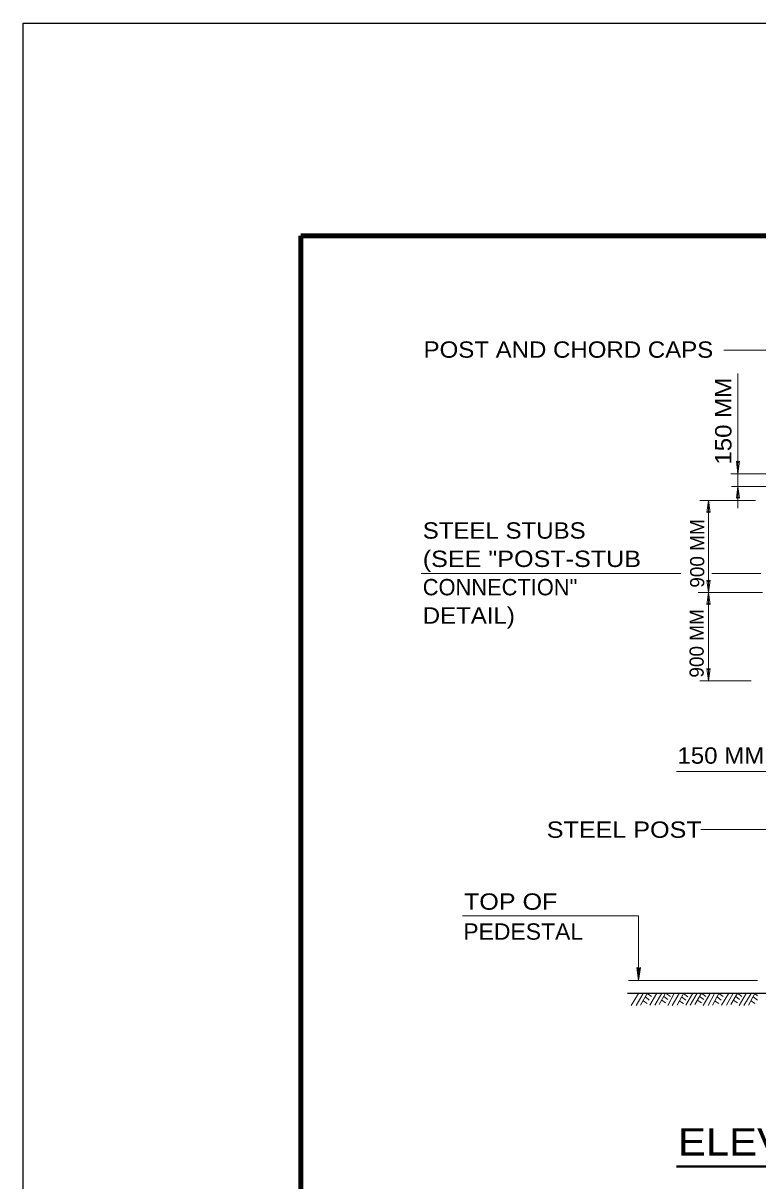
# Model space of a CAD drawing. Extents: x 312601.858 to 312602.699, y 144420.109 to 144420.704.
# Drawn here: x 312601.8578 to 312601.9927, y 144420.4911 to 144420.7035 of the extents above; entities that cross this region are included whole.
import ezdxf
from ezdxf.enums import TextEntityAlignment as Align

# ---------------------------------------------------------------- set-up
doc = ezdxf.new("R2010")
doc.units = 0
doc.header["$LTSCALE"] = 0.0012
for name, color, linetype, lineweight in [('1', 7, 'Continuous', 13), ('2', 7, 'Continuous', 25), ('39', 7, 'Continuous', 13)]:
    doc.layers.add(name, color=color, linetype=linetype, lineweight=lineweight)

msp = doc.modelspace()

# ---------------------------------------------------------------- hatches: boundary and pattern name
at = {"layer": '39'}
msp.add_hatch(color=256, dxfattribs=at).paths.add_polyline_path([(312601.9708, 144420.53), (312601.9712, 144420.5302), (312601.9708, 144420.5278), (312601.9705, 144420.5302)])

# ---------------------------------------------------------------- linework, layer by layer
at = {"layer": '1'}
for p, q in [((312601.9865, 144420.6435), (312601.9982, 144420.6435)), ((312601.9878, 144420.6208), (312601.9952, 144420.6208)), ((312601.9879, 144420.6185), (312601.9952, 144420.6185)), ((312601.9821, 144420.6159), (312601.9923, 144420.6159)), ((312601.9309, 144420.6025), (312601.9786, 144420.6025)), ((312601.9843, 144420.6025), (312601.9933, 144420.6025)), ((312601.9818, 144420.599), (312601.9936, 144420.599)), ((312601.9821, 144420.5828), (312601.9915, 144420.5828)), ((312601.9823, 144420.5555), (312601.9994, 144420.5555)), ((312601.969, 144420.5278), (312601.9927, 144420.5278)), ((312601.9695, 144420.5232), (312601.9708, 144420.5254)), ((312601.9704, 144420.5232), (312601.9717, 144420.5254)), ((312601.9712, 144420.5233), (312601.9724, 144420.5254)), ((312601.9724, 144420.5254), (312601.9732, 144420.5249)), ((312601.9729, 144420.5233), (312601.9742, 144420.5255)), ((312601.9738, 144420.5233), (312601.9751, 144420.5255)), ((312601.9746, 144420.5234), (312601.9758, 144420.5255)), ((312601.9758, 144420.5255), (312601.9767, 144420.5249)), ((312601.9762, 144420.5232), (312601.9774, 144420.5254)), ((312601.977, 144420.5232), (312601.9783, 144420.5254)), ((312601.9779, 144420.5233), (312601.9791, 144420.5254)), ((312601.9791, 144420.5254), (312601.9799, 144420.5248)), ((312601.9795, 144420.5233), (312601.9808, 144420.5255)), ((312601.9803, 144420.5233), (312601.9816, 144420.5255)), ((312601.9812, 144420.5234), (312601.9824, 144420.5255)), ((312601.9824, 144420.5255), (312601.9832, 144420.5249)), ((312601.9827, 144420.5232), (312601.984, 144420.5254)), ((312601.9836, 144420.5232), (312601.9848, 144420.5254)), ((312601.9844, 144420.5233), (312601.9856, 144420.5254)), ((312601.9856, 144420.5254), (312601.9864, 144420.5249)), ((312601.9861, 144420.5233), (312601.9874, 144420.5255)), ((312601.987, 144420.5233), (312601.9882, 144420.5255)), ((312601.9878, 144420.5234), (312601.989, 144420.5255)), ((312601.989, 144420.5255), (312601.9898, 144420.5249)), ((312601.9893, 144420.5232), (312601.9906, 144420.5254)), ((312601.9902, 144420.5232), (312601.9915, 144420.5254)), ((312601.991, 144420.5233), (312601.9922, 144420.5254)), ((312601.9922, 144420.5254), (312601.9927, 144420.525)), ((312601.9717, 144420.5241), (312601.9724, 144420.5236)), ((312601.9721, 144420.5248), (312601.9728, 144420.5242)), ((312601.9751, 144420.5242), (312601.9758, 144420.5237)), ((312601.9755, 144420.5249), (312601.9762, 144420.5243)), ((312601.9783, 144420.5241), (312601.9791, 144420.5236)), ((312601.9787, 144420.5248), (312601.9795, 144420.5242)), ((312601.9816, 144420.5242), (312601.9824, 144420.5237)), ((312601.982, 144420.5249), (312601.9828, 144420.5243)), ((312601.9848, 144420.5241), (312601.9856, 144420.5236)), ((312601.9853, 144420.5248), (312601.986, 144420.5242)), ((312601.9882, 144420.5242), (312601.989, 144420.5237)), ((312601.9887, 144420.5249), (312601.9894, 144420.5243)), ((312601.9915, 144420.5241), (312601.9922, 144420.5236)), ((312601.9919, 144420.5248), (312601.9927, 144420.5242))]:
    msp.add_line(p, q, dxfattribs=at)
at = {"layer": '1', "lineweight": 25}
msp.add_line((312601.9688, 144420.5255), (312602.0175, 144420.5255), dxfattribs=at)
at = {"layer": '1', "lineweight": 40}
msp.add_line((312601.9778, 144420.4937), (312602.169, 144420.4937), dxfattribs=at)
at = {"layer": '1'}
for points in [[(312601.9891, 144420.6392), (312601.9891, 144420.6208), (312601.9891, 144420.6185), (312601.9891, 144420.6145)], [(312601.9837, 144420.6159), (312601.9837, 144420.599), (312601.9837, 144420.5828)], [(312601.9778, 144420.5662), (312601.9964, 144420.5662), (312601.9994, 144420.5662)], [(312601.9385, 144420.5397), (312601.9708, 144420.5397), (312601.9708, 144420.5278)]]:
    msp.add_lwpolyline(points, dxfattribs=at)
for points in [[(312601.9894, 144420.6231), (312601.9891, 144420.6208), (312601.9888, 144420.6231), (312601.9891, 144420.6228)], [(312601.9888, 144420.6163), (312601.9891, 144420.6185), (312601.9894, 144420.6163), (312601.9891, 144420.6165)], [(312601.9834, 144420.6137), (312601.9837, 144420.6159), (312601.984, 144420.6137), (312601.9837, 144420.6139)], [(312601.984, 144420.6013), (312601.9837, 144420.599), (312601.9834, 144420.6013), (312601.9837, 144420.601)], [(312601.9834, 144420.5968), (312601.9837, 144420.599), (312601.984, 144420.5968), (312601.9837, 144420.597)], [(312601.984, 144420.5851), (312601.9837, 144420.5828), (312601.9834, 144420.5851), (312601.9837, 144420.5848)]]:
    msp.add_lwpolyline(points, close=True, dxfattribs=at)
at = {"layer": '39', "lineweight": 25}
for p, q in [((312601.8578, 144420.1095), (312601.8578, 144420.7035)), ((312601.8578, 144420.7035), (312602.6988, 144420.7035))]:
    msp.add_line(p, q, dxfattribs=at)
at = {"layer": '39', "lineweight": 158}
for p, q in [((312601.9088, 144420.1247), (312601.9088, 144420.6645)), ((312601.9088, 144420.6645), (312602.6838, 144420.6645))]:
    msp.add_line(p, q, dxfattribs=at)
at = {"layer": '39'}
msp.add_lwpolyline([(312601.9708, 144420.53), (312601.9712, 144420.5302), (312601.9708, 144420.5278), (312601.9705, 144420.5302)], close=True, dxfattribs=at)

# ---------------------------------------------------------------- texts
at = {"layer": '2'}
for s, height, width, p in [('POST AND CHORD CAPS', 0.003, 1.1, (312601.95795, 144420.6421)), ('150 MM', 0.003, 1.1, (312601.98595, 144420.5676)), ('STEEL POST', 0.003, 1.15, (312601.9682, 144420.554)), ('TOP OF', 0.003, 1.15, (312601.94735, 144420.5408)), ('PEDESTAL', 0.003, 1.05, (312601.94965, 144420.5353)), ('ELEVATION -TYPICAL CANTILEVER SIGN SUPPORT', 0.005, 1.15, (312602.07335, 144420.4957))]:
    msp.add_text(s, height=height, dxfattribs=dict(at, width=width)).set_placement(p, align=Align.CENTER)
at = {"layer": '2', "width": 1.1}
msp.add_text('150 MM', height=0.003, rotation=90, dxfattribs=at).set_placement((312601.9879, 144420.63045), align=Align.CENTER)
at = {"layer": '2'}
for s, width, p in [('STEEL STUBS', 1.1, (312601.9312, 144420.6089)), ('(SEE "POST-STUB', 1.15, (312601.9312, 144420.6037)), ('DETAIL)', 1.1, (312601.9312, 144420.5933))]:
    msp.add_text(s, height=0.003, dxfattribs=dict(at, width=width)).set_placement(p)
for p in [(312601.9829, 144420.5999), (312601.9828, 144420.5834)]:
    msp.add_text('900 MM', height=0.0026, rotation=90, dxfattribs=at).set_placement(p)
msp.add_text('CONNECTION"', height=0.003, dxfattribs=at).set_placement((312601.9312, 144420.5985))

doc.saveas('drawing.dxf')
